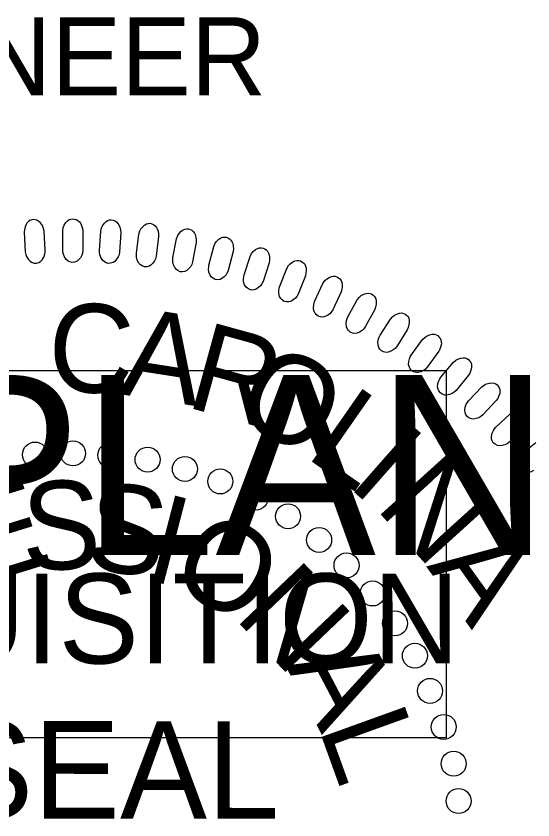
# Model space of a CAD drawing. Extents: x 505602 to 507286, y 483109 to 484209.
# Drawn here: x 507215 to 507248.1, y 484097.2 to 484148.7 of the extents above; entities that cross this region are included whole.
import ezdxf

# ---------------------------------------------------------------- set-up
doc = ezdxf.new("R2010")
doc.units = 0
for name, color, linetype in [('Sheet PE Seal Cell', 7, 'Continuous'), ('Sheet Profile CELL', 7, 'Continuous'), ('Sheet Sticker Incomplete CELL', 7, 'Continuous')]:
    doc.layers.add(name, color=color, linetype=linetype)

msp = doc.modelspace()

# ---------------------------------------------------------------- linework, layer by layer
at = {"layer": 'Sheet PE Seal Cell'}
for points in [[(507216.92, 484133.715), (507216.843, 484134.939), (507216.792, 484135.156), (507216.731, 484135.291), (507216.609, 484135.454), (507216.505, 484135.558), (507216.388, 484135.63), (507216.281, 484135.663), (507216.168, 484135.676), (507216.057, 484135.649), (507215.94, 484135.612), (507215.839, 484135.546), (507215.741, 484135.44), (507215.687, 484135.356), (507215.628, 484135.203), (507215.58, 484135.02), (507215.568, 484134.86), (507215.639, 484133.605), (507215.671, 484133.437), (507215.725, 484133.3), (507215.824, 484133.147), (507215.945, 484133.014), (507216.047, 484132.941), (507216.208, 484132.891), (507216.358, 484132.88), (507216.505, 484132.929), (507216.606, 484132.986), (507216.727, 484133.093), (507216.835, 484133.27), (507216.891, 484133.454), (507216.913, 484133.585)], [(507218.035, 484133.724), (507218.035, 484134.95), (507218.073, 484135.17), (507218.126, 484135.31), (507218.238, 484135.479), (507218.335, 484135.589), (507218.447, 484135.668), (507218.551, 484135.708), (507218.664, 484135.728), (507218.776, 484135.708), (507218.896, 484135.678), (507219, 484135.619), (507219.105, 484135.519), (507219.165, 484135.438), (507219.232, 484135.289), (507219.292, 484135.109), (507219.314, 484134.95), (507219.321, 484133.694), (507219.299, 484133.524), (507219.253, 484133.384), (507219.164, 484133.225), (507219.052, 484133.085), (507218.954, 484133.005), (507218.797, 484132.946), (507218.648, 484132.926), (507218.499, 484132.966), (507218.394, 484133.015), (507218.266, 484133.115), (507218.147, 484133.285), (507218.08, 484133.464), (507218.05, 484133.594)], [(507220.394, 484133.697), (507220.472, 484134.922), (507220.522, 484135.138), (507220.584, 484135.274), (507220.707, 484135.436), (507220.81, 484135.54), (507220.927, 484135.612), (507221.034, 484135.645), (507221.148, 484135.658), (507221.258, 484135.631), (507221.376, 484135.594), (507221.476, 484135.527), (507221.575, 484135.422), (507221.629, 484135.338), (507221.687, 484135.184), (507221.735, 484135.002), (507221.748, 484134.841), (507221.675, 484133.586), (507221.643, 484133.418), (507221.589, 484133.282), (507221.489, 484133.129), (507221.369, 484132.996), (507221.267, 484132.922), (507221.106, 484132.873), (507220.955, 484132.862), (507220.809, 484132.911), (507220.708, 484132.968), (507220.587, 484133.076), (507220.479, 484133.252), (507220.423, 484133.435), (507220.401, 484133.567)], [(507222.757, 484133.522), (507222.911, 484134.739), (507222.975, 484134.952), (507223.045, 484135.084), (507223.177, 484135.238), (507223.288, 484135.335), (507223.409, 484135.399), (507223.518, 484135.426), (507223.631, 484135.432), (507223.74, 484135.398), (507223.855, 484135.353), (507223.951, 484135.281), (507224.043, 484135.168), (507224.092, 484135.082), (507224.141, 484134.925), (507224.176, 484134.739), (507224.179, 484134.579), (507224.028, 484133.331), (507223.985, 484133.165), (507223.923, 484133.033), (507223.814, 484132.886), (507223.685, 484132.761), (507223.579, 484132.694), (507223.415, 484132.655), (507223.265, 484132.653), (507223.121, 484132.712), (507223.024, 484132.774), (507222.91, 484132.889), (507222.812, 484133.073), (507222.769, 484133.259), (507222.755, 484133.392)], [(507225.096, 484133.236), (507225.326, 484134.44), (507225.404, 484134.649), (507225.482, 484134.776), (507225.624, 484134.922), (507225.74, 484135.011), (507225.865, 484135.068), (507225.975, 484135.088), (507226.089, 484135.087), (507226.195, 484135.046), (507226.307, 484134.994), (507226.399, 484134.916), (507226.483, 484134.798), (507226.527, 484134.709), (507226.565, 484134.549), (507226.59, 484134.361), (507226.582, 484134.2), (507226.354, 484132.965), (507226.299, 484132.803), (507226.229, 484132.674), (507226.111, 484132.534), (507225.975, 484132.418), (507225.864, 484132.358), (507225.699, 484132.328), (507225.548, 484132.337), (507225.409, 484132.404), (507225.316, 484132.473), (507225.21, 484132.594), (507225.124, 484132.784), (507225.091, 484132.972), (507225.087, 484133.106)], [(507227.402, 484132.762), (507227.707, 484133.95), (507227.797, 484134.153), (507227.883, 484134.275), (507228.034, 484134.412), (507228.155, 484134.494), (507228.284, 484134.543), (507228.395, 484134.555), (507228.509, 484134.547), (507228.612, 484134.5), (507228.721, 484134.441), (507228.807, 484134.357), (507228.883, 484134.235), (507228.922, 484134.143), (507228.949, 484133.98), (507228.963, 484133.792), (507228.945, 484133.631), (507228.639, 484132.412), (507228.575, 484132.254), (507228.496, 484132.13), (507228.37, 484131.998), (507228.227, 484131.891), (507228.113, 484131.837), (507227.946, 484131.819), (507227.796, 484131.837), (507227.662, 484131.913), (507227.573, 484131.987), (507227.474, 484132.115), (507227.4, 484132.309), (507227.38, 484132.5), (507227.383, 484132.632)], [(507229.651, 484132.14), (507230.031, 484133.307), (507230.134, 484133.504), (507230.227, 484133.62), (507230.386, 484133.747), (507230.513, 484133.821), (507230.644, 484133.862), (507230.756, 484133.868), (507230.869, 484133.852), (507230.969, 484133.798), (507231.073, 484133.732), (507231.155, 484133.643), (507231.223, 484133.516), (507231.255, 484133.422), (507231.273, 484133.259), (507231.274, 484133.07), (507231.247, 484132.911), (507230.865, 484131.714), (507230.791, 484131.559), (507230.705, 484131.44), (507230.571, 484131.316), (507230.42, 484131.219), (507230.304, 484131.173), (507230.136, 484131.164), (507229.987, 484131.192), (507229.858, 484131.276), (507229.774, 484131.356), (507229.684, 484131.489), (507229.622, 484131.688), (507229.614, 484131.879), (507229.626, 484132.012)], [(507231.935, 484131.405), (507232.387, 484132.545), (507232.502, 484132.735), (507232.602, 484132.846), (507232.769, 484132.962), (507232.9, 484133.029), (507233.034, 484133.061), (507233.145, 484133.06), (507233.257, 484133.038), (507233.353, 484132.977), (507233.454, 484132.905), (507233.529, 484132.811), (507233.59, 484132.68), (507233.616, 484132.584), (507233.624, 484132.42), (507233.613, 484132.231), (507233.575, 484132.074), (507233.119, 484130.903), (507233.035, 484130.754), (507232.942, 484130.641), (507232.8, 484130.526), (507232.645, 484130.437), (507232.525, 484130.398), (507232.357, 484130.401), (507232.211, 484130.438), (507232.086, 484130.53), (507232.007, 484130.614), (507231.926, 484130.754), (507231.878, 484130.956), (507231.881, 484131.148), (507231.901, 484131.279)], [(507234.176, 484130.471), (507234.699, 484131.581), (507234.826, 484131.763), (507234.933, 484131.867), (507235.107, 484131.973), (507235.241, 484132.031), (507235.376, 484132.055), (507235.488, 484132.047), (507235.598, 484132.017), (507235.691, 484131.951), (507235.787, 484131.873), (507235.856, 484131.774), (507235.908, 484131.639), (507235.928, 484131.542), (507235.925, 484131.377), (507235.903, 484131.19), (507235.855, 484131.036), (507235.326, 484129.896), (507235.234, 484129.752), (507235.134, 484129.645), (507234.984, 484129.538), (507234.824, 484129.46), (507234.701, 484129.429), (507234.534, 484129.442), (507234.39, 484129.488), (507234.273, 484129.587), (507234.199, 484129.677), (507234.126, 484129.822), (507234.091, 484130.026), (507234.106, 484130.217), (507234.134, 484130.347)], [(507236.3, 484129.456), (507236.891, 484130.53), (507237.03, 484130.704), (507237.143, 484130.802), (507237.323, 484130.896), (507237.461, 484130.945), (507237.598, 484130.961), (507237.709, 484130.946), (507237.816, 484130.909), (507237.905, 484130.837), (507237.995, 484130.754), (507238.058, 484130.651), (507238.102, 484130.513), (507238.116, 484130.414), (507238.103, 484130.251), (507238.068, 484130.065), (507238.012, 484129.914), (507237.412, 484128.81), (507237.311, 484128.672), (507237.204, 484128.571), (507237.049, 484128.474), (507236.883, 484128.406), (507236.759, 484128.383), (507236.593, 484128.406), (507236.452, 484128.461), (507236.34, 484128.568), (507236.273, 484128.662), (507236.21, 484128.811), (507236.187, 484129.017), (507236.214, 484129.207), (507236.25, 484129.335)], [(507238.358, 484128.271), (507239.016, 484129.306), (507239.165, 484129.471), (507239.284, 484129.561), (507239.469, 484129.644), (507239.61, 484129.685), (507239.748, 484129.692), (507239.857, 484129.669), (507239.963, 484129.626), (507240.047, 484129.549), (507240.131, 484129.459), (507240.188, 484129.353), (507240.223, 484129.213), (507240.23, 484129.114), (507240.207, 484128.951), (507240.161, 484128.767), (507240.095, 484128.621), (507239.427, 484127.556), (507239.317, 484127.425), (507239.205, 484127.331), (507239.044, 484127.245), (507238.874, 484127.187), (507238.749, 484127.171), (507238.584, 484127.205), (507238.448, 484127.269), (507238.343, 484127.382), (507238.281, 484127.481), (507238.227, 484127.633), (507238.218, 484127.84), (507238.257, 484128.028), (507238.301, 484128.153)], [(507240.358, 484126.997), (507241.079, 484127.989), (507241.238, 484128.145), (507241.363, 484128.228), (507241.553, 484128.299), (507241.696, 484128.33), (507241.834, 484128.329), (507241.942, 484128.299), (507242.045, 484128.25), (507242.124, 484128.168), (507242.202, 484128.073), (507242.252, 484127.964), (507242.278, 484127.821), (507242.28, 484127.721), (507242.246, 484127.561), (507242.189, 484127.38), (507242.113, 484127.238), (507241.38, 484126.217), (507241.262, 484126.094), (507241.144, 484126.007), (507240.978, 484125.93), (507240.805, 484125.883), (507240.679, 484125.876), (507240.517, 484125.92), (507240.385, 484125.992), (507240.287, 484126.112), (507240.232, 484126.214), (507240.187, 484126.369), (507240.191, 484126.577), (507240.242, 484126.762), (507240.294, 484126.884)], [(507242.252, 484125.581), (507243.035, 484126.526), (507243.203, 484126.671), (507243.332, 484126.746), (507243.527, 484126.805), (507243.672, 484126.827), (507243.809, 484126.817), (507243.915, 484126.781), (507244.014, 484126.725), (507244.088, 484126.639), (507244.161, 484126.539), (507244.203, 484126.426), (507244.22, 484126.282), (507244.216, 484126.183), (507244.172, 484126.025), (507244.104, 484125.848), (507244.02, 484125.711), (507243.224, 484124.739), (507243.098, 484124.622), (507242.974, 484124.543), (507242.804, 484124.478), (507242.628, 484124.441), (507242.502, 484124.441), (507242.343, 484124.495), (507242.216, 484124.576), (507242.126, 484124.702), (507242.077, 484124.807), (507242.043, 484124.965), (507242.059, 484125.171), (507242.122, 484125.353), (507242.182, 484125.472)], [(507244.024, 484124.067), (507244.864, 484124.961), (507245.041, 484125.096), (507245.175, 484125.162), (507245.373, 484125.208), (507245.519, 484125.222), (507245.655, 484125.203), (507245.759, 484125.161), (507245.855, 484125.098), (507245.922, 484125.007), (507245.989, 484124.903), (507246.025, 484124.788), (507246.032, 484124.644), (507246.022, 484124.544), (507245.968, 484124.389), (507245.889, 484124.218), (507245.796, 484124.086), (507244.94, 484123.165), (507244.808, 484123.057), (507244.68, 484122.986), (507244.505, 484122.931), (507244.328, 484122.906), (507244.202, 484122.915), (507244.047, 484122.978), (507243.924, 484123.066), (507243.843, 484123.198), (507243.801, 484123.306), (507243.776, 484123.465), (507243.805, 484123.671), (507243.879, 484123.847), (507243.946, 484123.962)], [(507245.768, 484122.374), (507246.663, 484123.213), (507246.848, 484123.336), (507246.986, 484123.394), (507247.186, 484123.428), (507247.333, 484123.432), (507247.467, 484123.405), (507247.569, 484123.356), (507247.66, 484123.288), (507247.722, 484123.192), (507247.782, 484123.084), (507247.81, 484122.967), (507247.809, 484122.823), (507247.791, 484122.724), (507247.728, 484122.573), (507247.639, 484122.407), (507247.538, 484122.281), (507246.626, 484121.416), (507246.487, 484121.316), (507246.355, 484121.253), (507246.178, 484121.21), (507245.999, 484121.196), (507245.874, 484121.212), (507245.723, 484121.285), (507245.606, 484121.381), (507245.533, 484121.517), (507245.498, 484121.627), (507245.483, 484121.789), (507245.525, 484121.992), (507245.61, 484122.164), (507245.684, 484122.274)]]:
    msp.add_lwpolyline(points, close=True, dxfattribs=at)
msp.add_lwpolyline([(507248.177, 484119.618), (507248.032, 484119.527), (507247.895, 484119.472), (507247.715, 484119.44), (507247.536, 484119.437), (507247.413, 484119.461), (507247.266, 484119.544), (507247.156, 484119.647), (507247.092, 484119.787), (507247.063, 484119.9), (507247.059, 484120.061), (507247.114, 484120.261), (507247.209, 484120.428), (507247.29, 484120.533), (507247.38, 484120.627), (507248.326, 484121.409)], dxfattribs=at)
for centre in [(507216.263, 484120.628), (507218.692, 484120.707), (507221.081, 484120.587), (507223.47, 484120.307), (507225.858, 484119.709), (507228.127, 484118.911), (507230.396, 484117.875), (507232.466, 484116.679), (507234.456, 484115.164), (507236.208, 484113.531), (507237.879, 484111.737), (507239.312, 484109.825), (507240.585, 484107.753), (507241.557, 484105.503), (507242.432, 484103.193), (507243.069, 484100.842), (507243.386, 484098.452)]:
    msp.add_circle(centre, 0.801, dxfattribs=at)
at = {"layer": 'Sheet Sticker Incomplete CELL'}
msp.add_lwpolyline([(507095.597, 484102.505), (507095.597, 484126.005), (507242.597, 484126.005), (507242.597, 484102.505)], close=True, dxfattribs=at)

# ---------------------------------------------------------------- texts
at = {"layer": 'Sheet PE Seal Cell'}
for s, height, rotation, p in [('C', 5.669, 357.5877, (507217.01, 484124.718)), ('A', 5.669, 351.0983, (507221.585, 484124.51)), ('R', 5.669, 344.609, (507225.792, 484123.716)), ('O', 5.669, 331.6302, (507228.747, 484123.062)), ('L', 5.669, 325.1409, (507233.48, 484120.531)), ('I', 5.669, 318.6515, (507236.173, 484118.677)), ('N', 5.669, 312.1622, (507237.978, 484117.257)), ('E', 5.669, 17.1686, (507212.701, 484112.266)), ('S', 5.669, 1.289, (507215.468, 484113.225)), ('S', 5.669, 353.3492, (507219.329, 484113.327)), ('I', 5.669, 345.4094, (507223.13, 484112.695)), ('O', 5.669, 329.5298, (507224.633, 484112.523)), ('A', 5.669, 305.6728, (507241.298, 484113.477)), ('N', 5.669, 313.6502, (507228.945, 484110.219)), ('A', 5.669, 297.7707, (507232.282, 484107.138)), ('L', 5.669, 289.8309, (507234.406, 484103.143)), ('SEAL', 6.2363, 359.9814, (507210.585, 484097.331))]:
    msp.add_text(s, height=height, rotation=rotation, dxfattribs=at).set_placement(p)
at = {"layer": 'Sheet Profile CELL'}
msp.add_text('ENGINEER', height=5.0001, dxfattribs=at).set_placement((507196.142, 484143.624))
at = {"layer": 'Sheet Sticker Incomplete CELL'}
for s, height, p in [('INCOMPLETE PLANS', 11.52, (507104.547, 484114.205)), ('DO NOT USE FOR R/W ACQUISITION', 5.76, (507107.797, 484107.255))]:
    msp.add_text(s, height=height, dxfattribs=at).set_placement(p)

doc.saveas('drawing.dxf')
